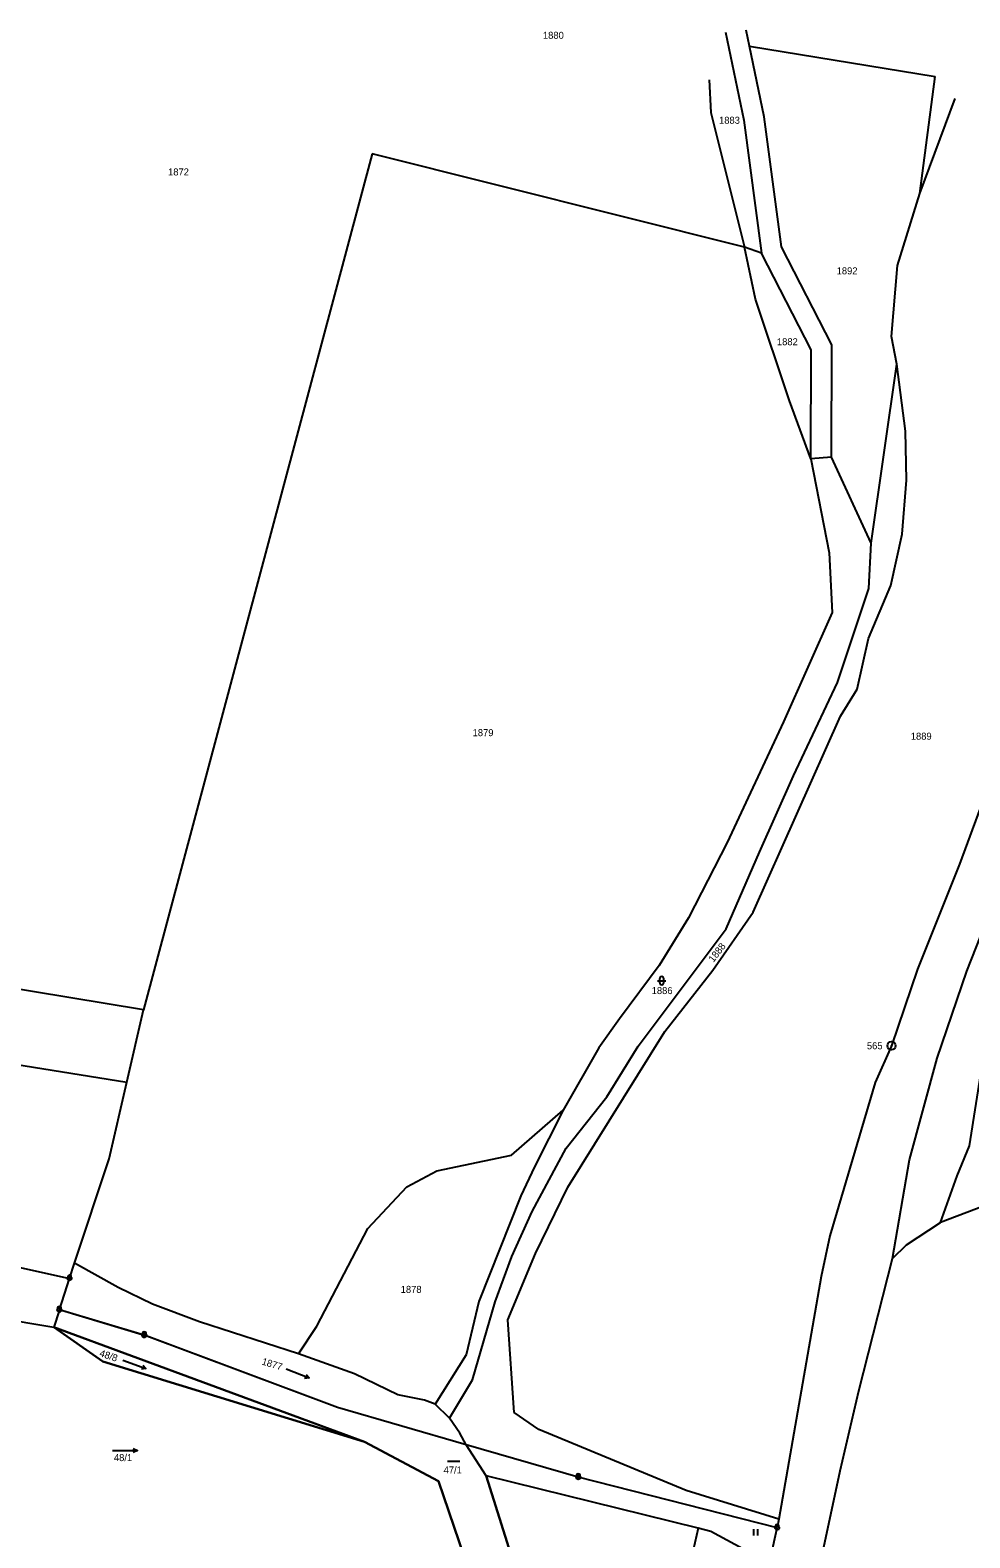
# Model space of a CAD drawing. Extents: x -801826 to -800592, y -1032871 to -1031813.
# Drawn here: x -801124.4 to -800896.7, y -1032178.1 to -1031812.6 of the extents above; entities that cross this region are included whole.
import ezdxf

# ---------------------------------------------------------------- set-up
doc = ezdxf.new("R2010")
doc.units = 0
for name, color, linetype in [('Vrstva 1', 7, 'Continuous'), ('Vrstva 17', 7, 'Continuous'), ('Vrstva 18', 7, 'Continuous'), ('Vrstva 24', 7, 'Continuous'), ('Vrstva 25', 7, 'Continuous')]:
    doc.layers.add(name, color=color, linetype=linetype)

msp = doc.modelspace()

# ---------------------------------------------------------------- linework, layer by layer
at = {"layer": 'Vrstva 1'}
for p, q in [((-800950.09, -1031816.46), (-800950.9, -1031812.56)), ((-800955.9, -1031813.07), (-800951.5, -1031834.37)), ((-800946.55, -1031833.6), (-800950.09, -1031816.46)), ((-800950.09, -1031816.46), (-800905.12, -1031823.81)), ((-800908.83, -1031852.17), (-800905.12, -1031823.81)), ((-800959.86, -1031824.63), (-800959.44, -1031832.5)), ((-800908.83, -1031852.17), (-800900.26, -1031829.16)), ((-800959.44, -1031832.5), (-800951.32, -1031865.19)), ((-800951.5, -1031834.37), (-800947.16, -1031866.66)), ((-800942.34, -1031865.12), (-800946.55, -1031833.6)), ((-801041.53, -1031842.55), (-801069.24, -1031946.32)), ((-800951.32, -1031865.19), (-801041.53, -1031842.55)), ((-800914.27, -1031869.61), (-800908.83, -1031852.17)), ((-800948.67, -1031877.8), (-800951.32, -1031865.19)), ((-800947.16, -1031866.66), (-800951.32, -1031865.19)), ((-800935.12, -1031890.1), (-800947.16, -1031866.66)), ((-800930.12, -1031888.87), (-800942.34, -1031865.12)), ((-800915.7, -1031886.86), (-800914.27, -1031869.61)), ((-800940.41, -1031902.42), (-800948.67, -1031877.8)), ((-800930.2, -1031916.07), (-800930.12, -1031888.87)), ((-800914.39, -1031893.55), (-800915.7, -1031886.86)), ((-800935.2, -1031916.48), (-800935.12, -1031890.1)), ((-800920.61, -1031936.94), (-800914.39, -1031893.55)), ((-800912.28, -1031909.79), (-800914.39, -1031893.55)), ((-800935.2, -1031916.48), (-800940.41, -1031902.42)), ((-800912.02, -1031921.64), (-800912.28, -1031909.79)), ((-800930.2, -1031916.07), (-800935.2, -1031916.48)), ((-800935.2, -1031916.48), (-800930.78, -1031939.3)), ((-800920.61, -1031936.94), (-800930.2, -1031916.07)), ((-800913.14, -1031934.73), (-800912.02, -1031921.64)), ((-800921.16, -1031947.94), (-800920.61, -1031936.94)), ((-800915.85, -1031947.25), (-800913.14, -1031934.73)), ((-800930.78, -1031939.3), (-800930.03, -1031953.73)), ((-800870.77, -1031937.34), (-800899.17, -1032014.78)), ((-801069.24, -1031946.32), (-801096.95, -1032050.09)), ((-800928.8, -1031970.76), (-800921.16, -1031947.94)), ((-800921.25, -1031960.05), (-800915.85, -1031947.25)), ((-800930.03, -1031953.73), (-800941.87, -1031980.28)), ((-800924, -1031972.36), (-800921.25, -1031960.05)), ((-800939.44, -1031993.36), (-800928.8, -1031970.76)), ((-800928.03, -1031978.93), (-800924, -1031972.36)), ((-800941.87, -1031980.28), (-800955.5, -1032009.5)), ((-800949.25, -1032026.42), (-800928.03, -1031978.93)), ((-800947.7, -1032011.84), (-800939.44, -1031993.36)), ((-800897.43, -1032040.71), (-800883.47, -1032005.21)), ((-800955.5, -1032009.5), (-800964.88, -1032027.76)), ((-800955.76, -1032030.49), (-800947.7, -1032011.84)), ((-800899.17, -1032014.78), (-800909.37, -1032040.21)), ((-801096.95, -1032050.09), (-801257, -1032023.94)), ((-800964.88, -1032027.76), (-800971.98, -1032039.39)), ((-800958.95, -1032040.47), (-800949.25, -1032026.42)), ((-800977.09, -1032058.88), (-800955.76, -1032030.49)), ((-800971.98, -1032039.39), (-800981.62, -1032052.3)), ((-800970.61, -1032055.33), (-800958.95, -1032040.47)), ((-800909.37, -1032040.21), (-800915.69, -1032058.82)), ((-800904.64, -1032061.81), (-800897.43, -1032040.71)), ((-801101, -1032067.63), (-801096.95, -1032050.09)), ((-800981.62, -1032052.3), (-800986.6, -1032059.34)), ((-800994.12, -1032093.14), (-800970.61, -1032055.33)), ((-801155, -1032059.05), (-801101, -1032067.63)), ((-800986.6, -1032059.34), (-800995.27, -1032074.47)), ((-800984.68, -1032071.22), (-800977.09, -1032058.88)), ((-800915.69, -1032058.82), (-800919.65, -1032067.69)), ((-800911.36, -1032086.45), (-800904.64, -1032061.81)), ((-800896.78, -1032083.1), (-800893.77, -1032064.12)), ((-801105.3, -1032086.21), (-801101, -1032067.63)), ((-800919.65, -1032067.69), (-800930.64, -1032104.93)), ((-800994.54, -1032083.63), (-800984.68, -1032071.22)), ((-801007.75, -1032085.35), (-800995.27, -1032074.47)), ((-800995.27, -1032074.47), (-801002.22, -1032088.21)), ((-800899.79, -1032090.38), (-800896.78, -1032083.1)), ((-801113.71, -1032111.56), (-801105.3, -1032086.21)), ((-801025.88, -1032089.13), (-801007.75, -1032085.35)), ((-801002.81, -1032099.04), (-800994.54, -1032083.63)), ((-800915.46, -1032110.41), (-800911.36, -1032086.45)), ((-801033.16, -1032093.04), (-801025.88, -1032089.13)), ((-801002.22, -1032088.21), (-801005.53, -1032095.23)), ((-800903.84, -1032101.64), (-800899.79, -1032090.38)), ((-801042.62, -1032103.11), (-801033.16, -1032093.04)), ((-801001.94, -1032109.18), (-800994.12, -1032093.14)), ((-801005.53, -1032095.23), (-801015.73, -1032120.83)), ((-800893.41, -1032097.71), (-800903.84, -1032101.64)), ((-801188.88, -1032098.79), (-801114.92, -1032115.22)), ((-801007.69, -1032109.91), (-801002.81, -1032099.04)), ((-800912.09, -1032107.07), (-800903.84, -1032101.64)), ((-801054.98, -1032126.77), (-801042.62, -1032103.11)), ((-800930.64, -1032104.93), (-800932.7, -1032114.75)), ((-800915.46, -1032110.41), (-800912.09, -1032107.07)), ((-801114.92, -1032115.22), (-801113.71, -1032111.56)), ((-801103.16, -1032117.42), (-801113.71, -1032111.56)), ((-801011.78, -1032120.94), (-801007.69, -1032109.91)), ((-801008.67, -1032125.3), (-801001.94, -1032109.18)), ((-800923.61, -1032142.51), (-800915.46, -1032110.41)), ((-801117.37, -1032122.85), (-801114.92, -1032115.22)), ((-800932.7, -1032114.75), (-800943.03, -1032173.63)), ((-801174.17, -1032117.88), (-801118.72, -1032127.06)), ((-801094.77, -1032121.47), (-801103.16, -1032117.42)), ((-801117.37, -1032122.85), (-801118.72, -1032127.06)), ((-801117.52, -1032123.33), (-801118.72, -1032127.06)), ((-801096.79, -1032129.01), (-801117.37, -1032122.85)), ((-801097.27, -1032128.87), (-801116.89, -1032122.99)), ((-801083.44, -1032125.78), (-801094.77, -1032121.47)), ((-801015.73, -1032120.83), (-801018.74, -1032133.79)), ((-801017.27, -1032139.84), (-801011.78, -1032120.94)), ((-801043.42, -1032154.83), (-801118.72, -1032127.06)), ((-801106.87, -1032135.4), (-801118.72, -1032127.06)), ((-801118.72, -1032127.06), (-801043.42, -1032154.83)), ((-801118.72, -1032127.06), (-801106.87, -1032135.4)), ((-801043.42, -1032154.83), (-801118.72, -1032127.06)), ((-801059.38, -1032133.53), (-801083.44, -1032125.78)), ((-801059.38, -1032133.53), (-801054.98, -1032126.77)), ((-801007.14, -1032147.71), (-801008.67, -1032125.3)), ((-801049.96, -1032146.51), (-801096.79, -1032129.01)), ((-801049.96, -1032146.51), (-801096.32, -1032129.19)), ((-801045.86, -1032138.4), (-801059.38, -1032133.53)), ((-801018.74, -1032133.79), (-801026.28, -1032145.72)), ((-801043.42, -1032154.83), (-801106.87, -1032135.4)), ((-801106.87, -1032135.4), (-801043.42, -1032154.83)), ((-801035.32, -1032143.49), (-801045.86, -1032138.4)), ((-801022.79, -1032149.11), (-801017.27, -1032139.84)), ((-801028.85, -1032144.77), (-801035.32, -1032143.49)), ((-801026.28, -1032145.72), (-801028.85, -1032144.77)), ((-800928.13, -1032161.88), (-800923.61, -1032142.51)), ((-801018.81, -1032155.56), (-801049.96, -1032146.51)), ((-801018.81, -1032155.56), (-801049.96, -1032146.51)), ((-801022.79, -1032149.11), (-801026.28, -1032145.72)), ((-801020.28, -1032152.74), (-801022.79, -1032149.11)), ((-801001.19, -1032151.88), (-801007.14, -1032147.71)), ((-801018.81, -1032155.56), (-801020.28, -1032152.74)), ((-800965.48, -1032166.64), (-801001.19, -1032151.88)), ((-801025.45, -1032164.36), (-801043.42, -1032154.83)), ((-801043.42, -1032154.83), (-801025.45, -1032164.36)), ((-800991.6, -1032163.46), (-801018.81, -1032155.56)), ((-801013.92, -1032163.13), (-801018.81, -1032155.56)), ((-801013.92, -1032163.13), (-801018.81, -1032155.56)), ((-800962.57, -1032175.77), (-801013.92, -1032163.13)), ((-801013.92, -1032163.13), (-800982.29, -1032263)), ((-800982.29, -1032263), (-801013.92, -1032163.13)), ((-800943.39, -1032175.71), (-800991.6, -1032163.46)), ((-800932.6, -1032182.67), (-800928.13, -1032161.88)), ((-801017.21, -1032188.54), (-801025.45, -1032164.36)), ((-801025.45, -1032164.36), (-801017.21, -1032188.54)), ((-800943.03, -1032173.63), (-800965.48, -1032166.64)), ((-800943.03, -1032173.63), (-800943.39, -1032175.71)), ((-800962.57, -1032175.77), (-800982.29, -1032263)), ((-800959.49, -1032176.59), (-800962.57, -1032175.77)), ((-800949.8, -1032181.86), (-800959.49, -1032176.59)), ((-800952.04, -1032215.07), (-800943.39, -1032175.71))]:
    msp.add_line(p, q, dxfattribs=at)
for centre, start, end in [((-801117.37, -1032122.85), 252.2208, 343.3365), ((-801096.79, -1032129.01), 163.3365, 339.5097)]:
    msp.add_arc(centre, 0.5, start, end, dxfattribs=at)
at = {"layer": 'Vrstva 24'}
for centre, radius in [((-800915.69, -1032058.82), 1), ((-800915.69, -1032058.82), 0.0439), ((-801114.92, -1032115.22), 0.5), ((-801114.92, -1032115.22), 0.0364), ((-801117.37, -1032122.85), 0.5), ((-801117.37, -1032122.85), 0.0364), ((-801096.79, -1032129.01), 0.5), ((-801096.79, -1032129.01), 0.0364), ((-800991.6, -1032163.46), 0.5), ((-800991.6, -1032163.46), 0.0364), ((-800943.39, -1032175.71), 0.5), ((-800943.39, -1032175.71), 0.0364)]:
    msp.add_circle(centre, radius, dxfattribs=at)
for centre in [(-801114.92, -1032114.85), (-801117.37, -1032122.48), (-801096.79, -1032128.64), (-800991.6, -1032163.09), (-800943.39, -1032175.34)]:
    msp.add_arc(centre, 0.45, 344.4473, 196.3778, dxfattribs=at)
at = {"layer": 'Vrstva 25'}
for p, q in [((-800972.37, -1032043.04), (-800970.37, -1032043.04)), ((-800971.87, -1032043.54), (-800971.87, -1032042.54)), ((-800970.87, -1032043.54), (-800970.87, -1032042.54)), ((-801102.02, -1032135.04), (-801096.38, -1032137.08)), ((-801062.39, -1032137.14), (-801056.81, -1032139.36)), ((-801104.46, -1032156.96), (-801098.46, -1032156.96)), ((-801023.33, -1032159.56), (-801020.33, -1032159.56)), ((-800949.12, -1032176.06), (-800949.12, -1032177.56)), ((-800948.09, -1032177.56), (-800948.09, -1032176.06))]:
    msp.add_line(p, q, dxfattribs=at)
for points in [[(-801097.15, -1032136.27), (-801096.38, -1032137.08), (-801097.49, -1032137.21)], [(-801057.56, -1032138.53), (-801056.81, -1032139.36), (-801057.93, -1032139.46)], [(-801099.46, -1032156.46), (-801098.46, -1032156.96), (-801099.46, -1032157.46)]]:
    msp.add_lwpolyline(points, dxfattribs=at)
for centre, start, end in [((-800971.37, -1032042.54), 0, 180), ((-800971.37, -1032043.54), 180, 0)]:
    msp.add_arc(centre, 0.5, start, end, dxfattribs=at)

# ---------------------------------------------------------------- texts
at = {"layer": 'Vrstva 17'}
msp.add_text('565', height=1.7, dxfattribs=at).set_placement((-800921.65, -1032059.67))
at = {"layer": 'Vrstva 18'}
for s, p in [('1880', (-801000.17, -1031814.66)), ('1883', (-800957.49, -1031835.26)), ('1872', (-801091.03, -1031847.79)), ('1892', (-800928.98, -1031871.77)), ('1882', (-800943.46, -1031888.96)), ('1879', (-801017.21, -1031983.75)), ('1889', (-800911.01, -1031984.6)), ('1886', (-800973.81, -1032046.29)), ('1878', (-801034.64, -1032118.74)), ('48/1', (-801104.15, -1032159.53)), ('47/1', (-801024.25, -1032162.53))]:
    msp.add_text(s, height=1.7, dxfattribs=at).set_placement(p)
for s, rotation, p in [('1888', 52.483, (-800958.84, -1032038.72)), ('48/8', 341.565, (-801107.8, -1032134.05)), ('1877', 342.858, (-801068.46, -1032136.07))]:
    msp.add_text(s, height=1.7, rotation=rotation, dxfattribs=at).set_placement(p)

doc.saveas('drawing.dxf')
